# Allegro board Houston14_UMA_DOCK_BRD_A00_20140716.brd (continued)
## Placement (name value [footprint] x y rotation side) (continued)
RV83  2.2K_0402_5%  [R_0402]  153.4 98.36 180 top
RV84  1M_0402_5%  [R_0402]  153.4 99.38 180 top
RV85  1M_0402_5%  [R_0402]  169 102.16 0 top
RV86  10K_0402_5%  [R_0402]  159.04 103.9 270 bottom
RV87  2.2K_0402_5%  [R_0402]  154.01 92.52 0 bottom
RV88  10K_0402_5%  [R_0402]  158.79 86.48 90 top
RV89  3.74K_0402_1%  [R_0402]  159.8 87.39 270 top
RV90  100K_0402_5%  [R_0402]  196.58 100.65 180 bottom
RV91  100K_0402_5%  [R_0402]  182.87 100.4 180 bottom
RV100  4.7K_0402_5%  [R_0402]  146.82 89.17 270 bottom
RV121  4.7K_0402_5%  [R_0402]  178.85 89.27 90 top
RV210  100K_0402_5%  [R_0402]  167.94 84.08 90 top
RV212  100K_0402_5%  [R_0402]  172.19 87.18 180 top
RV250  2.2K_0402_5%  [R_0402]  180.12 89.27 90 top
RV251  2.2K_0402_5%  [R_0402]  181.14 89.27 90 top
RV508  1M_0402_5%  [R_0402]  184.49 99.38 0 bottom
RV509  1M_0402_5%  [R_0402]  170.78 99.38 0 bottom
RV516  2.2K_0402_5%  [R_0402]  154.38 101.54 180 top
RV517  2.2K_0402_5%  [R_0402]  152.49 100.28 0 top
RV518  2.2K_0402_5%  [R_0402]  169.42 97.16 180 top
RV519  2.2K_0402_5%  [R_0402]  160.39 99.21 90 bottom
RZ5  100K_0402_5%  [R_0402]  174.08 82.62 0 top
RZ8  2.2K_0402_5%  [R_0402]  241.03 20.89 180 top
RZ9  2.2K_0402_5%  [R_0402]  241.03 19.88 180 top
RZ10  1M_0402_5%  [R_0402]  241.03 13.27 180 top
RZ14  100K_0402_5%  [R_0402]  276.14 52.85 270 top
RZ15  100K_0402_5%  [R_0402]  272.58 51.17 90 top
RZ16  100K_0402_5%  [R_0402]  180.58 82.87 180 top
RZ17  0_0402_5%  [R0402_0OHM]  183.98 63.31 0 top
RZ18  4.7K_0402_5%  [R_0402]  237.02 34.91 90 top
RZ19  4.7K_0402_5%  [R_0402]  237.02 37.86 270 top
RZ21  33_0402_5%  [R_0402]  242.05 56.96 180 top
RZ22  10K_0402_5%  [R_0402]  243.17 55.95 0 top
RZ24  10K_0402_5%  [R_0402]  253.02 90.95 270 top
RZ25  220_0402_5%  [R_0402]  292.7 42.99 0 bottom
RZ26  33_0402_5%  [R_0402]  183.98 64.33 0 top
RZ27  220_0402_5%  [R_0402]  250.99 90.95 270 top
RZ28  330_0402_5%  [R_0402]  292.77 43.75 0 top
RZ29  33_0402_5%  [R_0402]  183.98 62.3 0 top
RZ30  33_0402_5%  [R_0402]  183.98 60.26 0 top
RZ31  100K_0402_5%  [R_0402]  306.67 87.19 0 bottom
RZ32  150_0402_5%  [R_0402]  310.49 87.86 180 bottom
RZ33  220_0402_5%  [R_0402]  304.53 85.03 180 bottom
RZ34  220_0402_5%  [R_0402]  310.38 84.04 180 bottom
RZ35  33_0402_5%  [R_0402]  183.98 65.34 0 top
RZ37  100K_0402_5%  [R_0402]  279.97 52.86 270 top
RZ38  100K_0402_5%  [R_0402]  273.41 63.9 270 top
RZ39  10K_0402_5%  [R_0402]  284.98 93.03 180 top
RZ40  100K_0402_5%  [R_0402]  270.01 70.07 90 top
RZ41  0_0402_5%  [R_0402]  269.89 65.92 0 top
RZ42  0_0402_5%  [R0402_0OHM]  269.89 66.84 0 top
RZ43  0_0402_5%  [R0402_0OHM]  283.68 80.39 0 bottom
RZ44  0.01_1206_1%  [R_1206]  178.08 77.35 0 top
RZ46  0_0603_5%  [R_0603]  181.8 38.57 90 top
RZ47  0_0603_5%  [R0603_0OHM]  183.06 39.98 270 top
RZ51  0_0402_5%  [R0402_0OHM]  241.48 70.74 0 top
RZ56  0_0402_5%  [R_0402]  282.6 48.95 180 top
RZ57  0_0402_5%  [R0402_0OHM]  282.6 48.05 180 top
SW1  SS3-CMFTQR9_3P  [SW_SS3-CMFTQR9_3P]  228.6 68.89 0 bottom
SW3  SKRBAAE010_4P  [SW_SKRBAAE010_4P]  323.2 94.06 0 top
T8  PAD~D  [TPC12]  170.01 43.47 0 top
T9  PAD~D  [TPC12]  173.27 54.63 0 top
T10  PAD~D  [TPC12]  123.48 62.8 0 top
T11  PAD~D  [TPC12]  123.1 64.2 0 top
T12  PAD~D  [TPC12]  124.24 61.53 0 top
T13  PAD~D  [TPC12]  121.82 64.15 0 top
T14  PAD~D  [TPC12]  125.77 61.53 0 top
T15  PAD~D  [TPC12]  125.01 62.8 0 top
T16  PAD~D  [TPC12]  170.6 56.96 0 top
T21  PAD~D  [TPC12]  173.47 55.4 0 top
T22  PAD~D  [TPC12]  170.61 60.39 0 top
T27  PAD~D  [TPC12]  176.11 53.48 0 top
T28  PAD~D  [TPC12]  124.07 43.2 180 bottom
T29  PAD~D  [TPC12]  121.03 41.34 180 bottom
T30  PAD~D  [TPC12]  125.06 72.13 180 bottom
T31  PAD~D  [TPC12]  126 69.71 180 bottom
T33  PAD~D  [TPC12]  140.94 75.57 180 bottom
T34  PAD~D  [TPC12]  142.6 75.31 180 bottom
T35  PAD~D  [TPC12]  122.25 60.59 0 top
T74  PAD~D  [TPC12]  132.19 61.94 0 top
T75  PAD~D  [TPC12]  132.12 63.54 0 top
T76  PAD~D  [TPC12]  133.79 62.85 0 top
T77  PAD~D  [TPC12]  133.9 64.33 0 top
T87  PAD~D  [TPC12]  256.43 114.21 0 top
T88  PAD~D  [TPC12]  284.01 86.17 0 top
T89  PAD~D  [TPC12]  282.99 87.82 0 top
T96  PAD~D  [TPC12]  261.02 74.23 180 top
T97  PAD~D  [TPC12]  251.83 87.39 180 top
T98  PAD~D  [TPC12]  257.49 86.93 180 top
T99  PAD~D  [TPC12]  251.5 85.92 0 top
T108  PAD~D  [TPC12]  160.41 88.36 0 top
T109  PAD~D  [TPC12]  174.41 64.71 0 top
TL1  MHPC_NS692417  [MHPC_NS692417_24P]  309.39 89.99 180 bottom
UA1  -  [ALC3235-CG_MQFN48_6X6]  29.76 92.61 90 top
UC1  BDW-ULT-DDR3L_BGA1168  [BDW-ULT-DDR3L_BGA_1168P-T]  168.98 70.23 0 bottom
UC2  -  [W25Q64FVSSIQ_SO8]  199.02 55.57 270 bottom
UC3  -  [W25Q32FVSSIQ_SO8]  199.2 66.28 270 bottom
UC4  -  [74AHC1G09GW_TSSOP5]  176.7 58.85 90 top
UC5  TC7SH08FU_SSOP5~D  [TC7SH08FU_SSOP5]  184 52.79 270 top
UC6  TC7SH08FU_SSOP5~D  [TC7SH08FU_SSOP5]  188.95 47.93 90 top
UC7  -  [74CBTLV3126BQ_DHVQFN14_2P5X3]  107.04 35.17 90 top
UC8  -  [74AUP1G07GW_TSSOP5]  169.08 40.56 90 top
UD1  -  [74AUP1G07GW_TSSOP5]  143.17 2.46 90 top
UE1  ECE5048-LZY_DQFN132_11X11~D  [ECE5048-LZY_DQFN132_11X11]  258.17 84.89 180 top
UE2  -  [MEC5085-LZY_DQFN132_11X11]  263.3 55.75 90 top
UI1  SY6288D10CAC_MSOP8  [G547I2P81U_MSOP8]  56.65 104.55 270 top
UI2  SY6288D10CAC_MSOP8  [G547I2P81U_MSOP8]  247.99 117.2 270 bottom
UI3  -  [TPS2544RTER_WQFN16_3X3]  305.32 78.54 270 top
UI4  -  [PI3USB3102ZLEX_TQFN32_6X3]  187.52 92.48 0 top
UI5  -  [NX3DV221GM_XQFN10U10_2X1P55]  162.84 105.2 0 bottom
UL1  WGI218LM-QQ89-B0_QFN48_6X6~D  [WGI217LM-QPN9-A2_QFN48_6X6]  275.7 88.12 270 top
UL2  TC7SH08FU_SSOP5~D  [TC7SH08FU_SSOP5]  285.17 83.82 180 top
UL4  -  [PI3L720ZHEX_TQFN42_9X3P5]  241.55 101.07 0 top
UN1  -  [LNG3DMTR_LGA16_3X3]  286.25 57.74 90 top
UN2  -  [PI3EQX6741STZDEX_TQFN20_4X4]  293.51 58.72 270 top
UN3  TPS22967DSGR_SON8_2X2  [TPS22965DSGR_SON8_2X2]  304.94 53.29 180 top
UR1  -  [OZ777FJ2LN_QFN48_6X6]  306.61 66.02 270 top
UV2  -  [AP2330W-7_SC59-3]  98.03 103.26 180 top
UV4  -  [AP2330W-7_SC59-3]  272.58 108.85 180 top
UV7  -  [PS8338BQFN60GTR-A0_QFN60_5X9]  144.05 91.56 180 bottom
UV8  VMM3320BJGR_BGA168  [VMM3320BJGR_BGA_168P-NH]  156.85 98.38 0 top
UV9  W25X10CVSNIG_SO8  [W25X10BVSNIG_SO8]  151.93 99.93 0 bottom
UV11  -  [PI3C3125LEX_TSSOP14]  187.38 99.72 90 bottom
UV12  -  [PI3C3125LEX_TSSOP14]  173.92 99.72 90 bottom
UV16  TS3V713ELRTGR_WQFN32_6X3  [PI3V713-AZLEX_TQFN32_6X3]  176.09 92.46 0 top
UV24  -  [AP2821KTR-G1_SOT23-5]  85.32 95.27 180 top
UZ1  AT97SC3205_TSSOP28~D  [AT97SC3205_TSSOP28]  193.95 59.09 90 top
UZ2  APE8990GN3B_SON14_2X3  [TPS22966DPUR_SON14_2X3]  267.57 72.96 0 top
UZ3  APE8990GN3B_SON14_2X3  [TPS22966DPUR_SON14_2X3]  275.81 61.54 180 top
UZ5  -  [RT9818A-44GU3_SC70-3]  241.91 54.17 90 top
UZ6  TC7SH08FU_SSOP5~D  [TC7SH08FU_SSOP5]  246.31 53.59 180 top
UZ7  TPS22967DSGR_SON8_2X2  [TPS22965DSGR_SON8_2X2]  177.75 80.57 270 top
UZ8  APE8990GN3B_SON14_2X3  [TPS22966DPUR_SON14_2X3]  184.45 34.86 0 top
UZ9  APE8990GN3B_SON14_2X3  [TPS22966DPUR_SON14_2X3]  215.44 88.32 0 top
UZ10  TC7SH08FU_SSOP5~D  [TC7SH08FU_SSOP5]  295.66 45.15 270 top
UZ11  -  [TC7SH08FU_SSOP5]  285.56 48.18 90 top
YC1  32.768KHZ_12.5PF_9H03220008  [Y_9H03220008_2P]  188 45.26 270 bottom
YC2  24MHZ_12PF_X3G024000DC1H  [Y_X3G024000DC1H_4P]  155.4 82.45 0 bottom
YE1  32.768KHZ_12.5PF_Q13FC135000040  [Y_Q13FC135000040_2P]  261.42 47.82 0 top
YL1  25MHZ_18PF_7V25000034  [Y_7V25000034_4P]  268.86 81.13 90 top
YV2  27MHZ_12PF_X1E000021042600  [Y_X1E000021042600_4P]  148.08 89.3 270 top

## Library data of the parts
C33 PC21 PC22 = C_0805
C42 C43 C319 CA12 CA13 CA54 CC3 CC14 CC15 CC24 CC83 CC97 CC100 CC101 CI38 CI414-CI419 CN3 CN4 CV115 CV118 CV374 CZ65-CZ68 PC20 PC106 PC206 PC311 PC520 PC521 PC732 = C_0402
C263 = C_0402: room: SIM
C294-C316 = C_0402: room: DOCK
C317 C318 = C_0603: room: DOCK
CA1-CA4 = C_0402: room: AJACK
CA5 CA6 = C_0402: room: CAM
CA7 CV1-CV6 CV8 CV10 CV11 CZ1 = C_0402: room: EDP
CA8 CA11 CA17 CA19 CA22-CA24 CA27 CA28 CA30 CA33 CA35 CA41 CA45 CA47 CA50 CV61 CV62 = C_0402: room: CODEC
CA9 CA10 CA16 CA18 CA25 CA26 CA29 CA31 CA43 CA44 CA46 CA48 CA49 CA51-CA53 = C_0603: room: CODEC
CC1 CC2 CC4 CC5 CC8 CC11-CC13 CC17-CC22 CC25-CC28 CC35 CC37 CC40 CC43 CC44 CC48-CC50 CC52-CC54 CC57-CC59 CC61 CC65 CC66 CC68-CC73 CC78 CC80 CC82 = C_0402: room: CPU
CC6 CC7 CC9 CC10 = C_0402: room: SPI
CC23 CC79 CC84 CC85 CC94 CC95 CI420-CI422 CV377-CV380 = C_0603
CC29-CC34 CC36 CC47 CC51 CC55 CC56 CC60 CC62-CC64 = C_0603: room: CPU
CC39 PC207 = C_D2: room: CPU
CC41 CC42 = C_APXK2R5ARA331MF451: room: CPU
CC67 CC77 CC81 = C_1206: room: CPU
CD1-CD11 CD21-CD27 CD30-CD44 CD54-CD60 CD63 CD64 = C_0402: room: MEMORY
CD12-CD19 CD28 CD29 CD45-CD52 CD61 CD62 = C_0603: room: MEMORY
CD20 CD53 = C_D2: room: MEMORY
CE1 CE7 = C_0603: room: SIO
CE2-CE6 CE8 CE9 = C_0402: room: SIO
CE10-CE20 CE22-CE30 CE34 CE40 CE44 CE45 CZ34 CZ35 = C_0402: room: KBC
CE21 CE31 = C_0603: room: KBC
CE32 = C_0603: room: FAN
CE35-CE39 CE46 = C_0402: room: THERMAL
CI1 CI8 CI14 = C_1206: room: USB
CI3-CI5 CI7 CI10 CI12 CI13 CI16 CI17 CI19 CI27 CI28 = C_0402: room: USB
CI6 CI11 = C_0603: room: USB
CL1-CL3 CL5 CL6 CL8-CL11 CL13-CL15 CL25-CL27 CZ62 CZ63 = C_0402: room: LAN
CL4 CL7 CL12 = C_0603: room: LAN
CL16 CL17 CL20 CL21 = C_0603: room: LOM
CL18 = C_0402: room: LOM
CL19 CV13 CV14 CV17 CV18 CV21-CV23 CV26 CV28 CV29 CZ2 = C_0402: room: HDMI
CL22 = C_1808: room: LOM
CMOS1 = SHORTPADS-S: User Part Number: PART#; room: CPU
CN1 = C_0603: room: HDD
CN2 CN13-CN20 CN23-CN26 CN29 CN30 = C_0402: room: HDD
CR1 CR7 CR9 CR14 CR18 CR34 = C_0603: room: OZ777
CR2-CR4 CR6 CR8 CR10 CR13 CR15 CR17 CR19 CR21-CR27 CR31 CR35 = C_0402: room: OZ777
CV7 CV9 CV12 = C_0603: room: EDP
CV27 = C_0603: room: HDMI
CV50-CV59 CV124-CV128 CV144 = C_0402: room: CRT
CV60 CV66 CV69-CV80 CV145-CV150 CV152 CV153 CV156 CV157 = C_0402: room: DP12412
CV82 CV87 CV90 CV94 CV101 = C_0603: room: DP2320
CV83-CV86 CV88 CV89 CV91-CV93 CV95-CV100 CV102-CV111 CV113 CV114 = C_0402: room: DP2320
CV119-CV123 = C_0402: room: DP125
CZ4-CZ7 CZ9 = C_0402: room: TPM
CZ10-CZ12 = C_0402: room: USH
CZ13-CZ18 CZ20-CZ22 CZ32 CZ33 CZ58 CZ59 = C_0402: room: WLAN
CZ19 = C_0603: room: WLAN
CZ23-CZ25 CZ41 CZ49 CZ50 = C_0402: room: 3.3V_SUS_SOURCE
CZ27-CZ31 = C_0402: room: KB_TP
CZ36 CZ37 CZ40 CZ44 CZ47 = C_0402: room: 3.3V_ALW_PCH_SOURCE
CZ38 = C_0603: room: 3.3V_SUS_SOURCE
CZ39 = C_0402: room: 1.05V_RUN_SOURCE
CZ42 CZ43 = C_0402: room: 3.3V_M_SOURCE
CZ45 = C_0402: room: 5V_RUN_SOURCE
CZ46 = C_0402: room: 3.3V_RUN_SOURCE
CZ48 = C_0402: room: LED
CZ51-CZ53 CZ55 = C_0402: room: WWAN
CZ54 = C_0603: room: WWAN
CZ56 = C_MP6VLPB150MB4: room: WWAN
CZ57 = C_B2: room: WWAN
CZ64 = C_0402: room: +1.05V_RUN_SOURCE
D19 = RB751S40T1G_SOD523-2: room: DOCK
D20 = L30ESD24VC3-2_SOT23-3: room: DOCK
DA1-DA3 = L03ESDL5V0CC3-2_SOT23-3: room: AJACK
DA4 DA5 = RB751S40T1G_SOD523-2: room: CODEC
DA6 DA7 = L03ESDL5V0CC3-2_SOT23-3: room: CODEC
DE1 = RB751S40T1G_SOD523-2: room: FAN
DI1 DI4 DI6 = L05ESDL5V0NA-4_SLP2510P8-10-9: room: USB
DI2 DI3 DI5 = AZC199-02SPR7G_SOT23-3: room: USB
DV1-DV3 = BAT54CW_SOT323-3: room: EDP
DV4 = AZC199-02SPR7G_SOT23-3: room: EDP
DV5 DV6 = PJDLC05C_SOT23-3: room: CRT
DZ1 DZ2 DZ5 DZ6 = RB751S40T1G_SOD523-2: room: WLAN
DZ3 DZ4 = RB751S40T1G_SOD523-2: room: LED
FD1-FD4 = FIDUCIAL_C40M80: room: LED
H1 H3 H6-H8 = H_2P8: room: LED
H2 H18 = H_2P4: room: LED
H4 H19 = H_4P0: room: LED
H9 H22 = H_2P8
H10 = H_3P8
H11-H13 = H_3P8: room: LED
H15 H17 = H_3P2: room: LED
H20 = H_2P5N: room: LED
H24 = H_3P3
JAPS1 = ACES_50506-01841-P01_18P: room: CPU
JCRT1 = C-H_13-122015XXCP-A_15P-T: room: CRT
JDEG1 JLPDE1 = HB_A531015-SCHR21_10P: room: SIO
JDIMM1 JDIMM2 = BELLW_80001-1021_204P: room: CPU
JDOCK1 = JAE_WD2F144WB5R400_144P: room: DOCK
JEDP1 = ACES_50398-04041-001_40P: room: EDP
JFAN1 = ACES_50271-0040N-001_4P: room: THERMAL
JHDMI1 = CONCR_099BKAC19YBLCNF_19P-T: room: HDMI
JHP1 = SINGA_2SJ3080-039111F_6P-T: room: CODEC
JKBTP1 = E-T_6705K-Y16N-00L_16P: room: SIO
JLED1 = E-T_6705K-Y10N-00L_10P-T: room: LED
JLOM1 = SANTA_130456-511_13P-T: room: LAN
JNGFF1 = BELLW_80148-3221_67P-T: room: WLAN
JNGFF2 = BELLW_80149-4221_67P-T: room: WWAN
JRTC1 = TYCO_2-1775293-2_2P: room: ETY-ROOM
JSATA1 = STARC_115B20-000000-G2-R_20P-T: room: HDD
JSD1 = T-SOL_156-2000302608_19P_NR-S: room: OZ777
JSIM1 = T-SOL_159-1201300600_8P-T: room: WWAN
JSPI1 = E-T_6705K-Y20N-00L_20P: room: FLASH ROM
JSPK1 = ACES_50279-0040N-001_4P: room: CODEC
JTAG1 = SHORTPADS: User Part Number: PART#; room: KBC
JUSB1 JUSB2 = C-K_26210-8K1A-02_9P-T: room: USB
JUSB3 = SINGA_2UB1641-000111F_9P-T: room: USB
JUSH1 = E-T_6705K-Y20N-00L_20P: room: TPM
JXDP1 = SAMTE_BSH-030-01-L-D-A_60P: room: CPU
LA2 LA3 = MURAT_BLM15BD601SN1D_2P: room: AJACK
LA5 = MURAT_BLM15PX600SN1D_2P: room: CODEC
LA6-LA9 = MURAT_BLM15PX330SN1D_2P: room: CODEC
LA10 LA11 = MURAT_BLM15PX330SN1D_2P
LC1-LC5 = MURAT_LQM2MPN2R2NG0L_2P: room: CPU
LED3 = LED_LTW-193ZDS5_2P: room: LED
LI1-LI9 = MURAT_DLW21HN900HQ2L_4P: room: USB
LL1 = TAIYO_BRC2012T4R7MD_2P: room: LAN
LV1 = MURAT_BLM15BB221SN1D_2P: room: EDP
LV3 LV6 LV9 LV12 = MURAT_DLW21HN900HQ2L_4P: room: HDMI
LV16-LV18 = MURAT_BLM15BB470SN1D_2P: room: CRT
LV19 LV20 = MURAT_BLM15AG121SN1D_L0402_2P: room: CRT
LV22-LV25 = MURAT_BLM15PX181SN1D_2P: room: DP2320
LV27 = MURAT_DLW21HN900HQ2L_4P: room: TOUCH
LZ1 = MURAT_DLW21HN900HQ2L_4P: room: CAM
MIC1 = KNOW_SPM1437HM4H-6_6P: room: CPU
PBATT1 = DEREN_40-42251-01001RHF_10P-T: room: ETY-ROOM
PC1 PC9 = C_0603: room: P_DCIN
PC3 PC4 = C_0402: room: P_DCIN
PC5 = C_0805: room: P_DCIN
PC10 PC101 PC102 PC200 PC201 PC205 PC303 PC305-PC308 PC401 PC404 = C_0805: room: ETY-ROOM
PC100 PC109-PC111 PC114 PC117-PC119 PC204 PC209 PC211 PC301 PC302 PC309 PC310 PC500 PC505 PC507 PC509 PC510 = C_0603: room: ETY-ROOM
PC105 PC203 PC212 PC214 PC215 PC300 PC304 PC400 PC402 PC403 PC502-PC504 PC506 PC511-PC514 PC737 PC741 = C_0402: room: ETY-ROOM
PC113 PC115 = C_APXK6R3ARA221MF451: room: 3V5V
PC208 PC721 = C_0603: room: ADP3209
PC213 PC501 PC805 PC810 = C_0402: room: CPU_CORE
PC508 = C_0603: room: CPU_CORE
PC515-PC518 = C_0805: room: CPU_CORE
PC519 = C_D: room: ETY-ROOM
PC700 PC701 PC710 PC712 PC722 = C_0603: room: CHARGER
PC702 PC703 PC711 PC713 PC718 PC719 PC726-PC728 = C_0402: room: CHARGER
PC704-PC709 PC714-PC717 PC723-PC725 = C_0805: room: CHARGER
PC729 PC813 PC815 PC816 = C_0603: room: P_SELECTOR
PC807 = C_0805: room: P_SELECTOR
PC809 PC817 = C_0402: room: P_SELECTOR
PC900-PC904 PC913-PC917 = C_0805: room: CPU
PC966 = C_D2
PD1 PD2 = TVNST52302AB0_SOT523-3: room: ETY-ROOM
PD3 = BAS40-05W_SC70-3: room: ETY-ROOM
PD4 = RB751V-40_SOD323-2: room: P_DCIN
PD5 = AZC199-02SPR7G_SOT23-3
PD702 PD704 PD705 = SDMK0340L-7-F_SOD323-2
PD800 PD808 = PDS5100H-13_POWERDI5-3: room: P_SELECTOR
PD813 = SDMK0340L-7-F_SOD323-2: room: ETY-ROOM
PD815 = BAT54CW_SOT323-3: room: ETY-ROOM
PD817 = BAT54CW_SOT323-3
PH500 PH501 PR100-PR102 PR104-PR107 PR114 PR201 PR205 PR206 PR209 PR303 PR307 PR310 PR400-PR403 PR500 PR502 PR512-PR516 PR527-PR529 PR706 PR707 PR722 PR737 PR738 PR745 PR864 = R_0402: room: ETY-ROOM
PJP1 PJP100-PJP102 PJP203 PJP204 PJP300 = JUMP_43X118: room: ETY-ROOM
PJP4 PJP5 = JUMP_43X39: room: HDD
PJP6 PJP9 PJP13 PJP26 = JUMP_43X79: room: CODEC
PJP7 PJP29 PJP35 = JUMP_43X39
PJP10 PJP17 PJP20 PJP24 PJP25 PJP32 = JUMP_43X39: room: CODEC
PJP11 = JUMP_43X39: room: TPM
PJP12 = JUMP_43X39: room: LAN
PJP14 = JUMP_43X39: room: SIO
PJP15 PJP16 = JUMP_43X39: room: KBC
PJP18 PJP21 PJP22 = JUMP_43X118: room: CODEC
PJP23 = JUMP_43X39: room: CPU
PJP36 = JUMP_43X118
PJP200 PJP302 = JUMP_43X79: room: DDR_VTT_0.75V
PJP201 PJP202 PJP400 PJP401 = JUMP_43X39: room: VGA_CORE
PJP500 = JUMP_43X118: room: CHARGER
PJP700 = JUMP_43X118-NPM: room: CHARGER
PJP701 = JUMP_43X39: room: CHARGER
PJPDC1 = CVILU_CI0805M1HRC-NH_5P-T: room: ETY-ROOM
PL1 PL2 PL4 = TAIYO_FBMJ4516HS720NT_2P: room: P_DCIN
PL3 = MURAT_BLM15AG102SN1D_2P: room: P_DCIN
PL100 = L_5X5X3_M_2P-NPM: room: ETY-ROOM
PL101 PL200 = PANAS_ETQP3W2R2WFN_2P: room: ETY-ROOM
PL102 = PANAS_ETQP3W2R2WFN_2P: room: VDDCI
PL301 PL700 = L_5X5X3_M_2P: room: ETY-ROOM
PL500 = PANAS_ETQP4LR15AFM_4P: room: ETY-ROOM
PL501 = FBMA-L11-453215800LMA90T_2P-NPM: room: CPU_CORE
PL701 = TOKO_FDVE1040-H-3R3M-P3_2P: room: ETY-ROOM
PQ1 = SI2301CDS-T1-GE3_SOT23-3: room: P_DCIN
PQ2 = FDV301N-G_SOT23-3: room: P_DCIN
PQ3 = MMST3904-7-F_SOT323-3: room: P_DCIN
PQ4 PQ826 = FDMC6679AZ_MLP8-5: room: ETY-ROOM
PQ6 = IMD2AT-108_SC74-6: room: ETY-ROOM
PQ100 PQ101 = SIS412DN-T1-GE3_POWERPAK8-5: room: ETY-ROOM
PQ102 PQ103 = SI7716ADN-T1-GE3_POWERPAK8-5: room: ETY-ROOM
PQ200 = SIS412DN-T1-GE3_POWERPAK8-5
PQ201 = SI7716ADN-T1-GE3_POWERPAK8-5
PQ700 = SI4835DDY-T1-GE3_SO8: room: CHARGER
PQ701 PQ702 = NTR4502PT1G_SOT23-3: room: ETY-ROOM
PQ703 = NTGD4161PT1G_TSOP6: room: ETY-ROOM
PQ705 = AON6970_DFN5X6D-8-7
PQ800 = SI4835DDY-T1-GE3_SO8: room: ETY-ROOM
PQ806 PQ813 = DMN65D8LDW-7_SOT363-6: room: P_SELECTOR
PQ810 PQ815 = FDS6679AZ-G_SO8: room: ETY-ROOM
PQ814 = NTR4502PT1G_SOT23-3: room: P_SELECTOR
PQ816 = DMN65D8LW-7_SOT323-3: room: DC_IN
PQ817 = DMN65D8LDW-7_SOT363-6: room: ETY-ROOM
PQ829 = SI2301CDS-T1-GE3_SOT23-3: room: P_SELECTOR
PQ832 = DMN65D8LW-7_SOT323-3: room: ETY-ROOM
PR1 PR2 PR7-PR15 PR17 PR18 PR863 = R_0402: room: P_DCIN
PR6 PR811 PR812 PR842 PR843 PR845 PR848 PR850 PR851 PR853-PR855 PR857 PR859 = R0402_0OHM: room: P_DCIN
PR16 = R_0805: room: P_DCIN
PR103 PR108 PR113 PR207 PR210 PR520 PR531 PR532 PR534 PR536 PR539 PR700 PR702 PR895 = R0402_0OHM: room: ETY-ROOM
PR109 PR110 PR200 PR517 PR519 = R_0603: room: CPU_CORE
PR111 PR112 PR203 PR305 = R_1206: room: ETY-ROOM
PR202 PR526 = R_0603: room: ETY-ROOM
PR204 RZ47 = R0603_0OHM
PR306 PR308 = R_0402: room: 1P5V
PR309 PR315 PR518 PR524 PR525 PR788 PR799 R6 R41 R273 RA40 RA44 RC27 RC92 RC247 RC300-RC306 RE84 RE86 RE88 RE274 RE276 RE277 RE280 RE281 RE283 RL29 RL30 RN6 RN7 RN19-RN25 RR15 RV100 RV210 RV212 RV250 RV251 RV516-RV519 RZ41 RZ56 = R_0402
PR312 = R0603_0OHM: room: CPU_CORE
PR313 RA45 RC26 RE275 RE279 RE282 RZ42 RZ43 RZ51 RZ57 = R0402_0OHM
PR501 PR503-PR511 PR521 PR523 PR535 = R_0402: room: GPU_CORE
PR522 = R_1206: room: CPU_CORE
PR701 PR721 = R_1206_4P-D: room: ETY-ROOM
PR703 PR710 PR711 PR713 PR715 PR725 PR729 PR740 = R_0402: room: CHARGER
PR704 PR705 PR709 PR714 PR716-PR718 PR720 PR728 PR743 = R0402_0OHM: room: CHARGER
PR708 PR726 = R_1206: room: CHARGER
PR712 = R_0603: room: 3V5V
PR723 = R_0603: room: CHARGER
PR810 PR813-PR816 PR818 PR819 PR822 PR826-PR830 PR844 PR846 PR858 PR874 = R_0402: room: P_SELECTOR
PR831 PR832 PR838 PR847 PR860 = R_0603: room: P_DCIN
PR835 = R_0805: room: P_SELECTOR
PRP2 = RP_0804_8P4R: room: ETY-ROOM
PT1 PT2 T99 T109 = TPC12
PU1 = TS5A63157DCKR_SC70-6: room: P_DCIN
PU100 = TPS51285BRUKR_QFN20_3X3: room: ETY-ROOM
PU200 = RT8207MZQW_WQFN20_3X3: room: ETY-ROOM
PU300 = SY8208DQNC_QFN10_3X3: room: ETY-ROOM
PU400 = APL5930KAI-TRG_SO8: room: ETY-ROOM
PU500 = TPS51622RSM_QFN32_4X4: room: CPU_CORE
PU501 = CSD97374CQ4M_SON8_3P5X4P5: room: ETY-ROOM
PU700 = BQ24715URUYR_WQFN28_4X4: room: ETY-ROOM
PU800 = CD3301RHHR_QFN36_6X6: room: P_SELECTOR
PU804 PU806 = TC7SH08FU_SSOP5: room: PCH
QA1 = L2N7002WT1G_SC-70-3: room: CODEC
QA2 QA3 = DMN66D0LDW-7_SOT363-6: room: CODEC
QC1 = DMN66D0LDW-7_SOT363-6: room: CPU
QD1 = L2N7002WT1G_SC-70-3: room: MEMORY
QE2 = DMN66D0LDW-7_SOT363-6: room: THERMAL
QE3-QE7 = MMBT3904WT1G_SC70-3: room: THERMAL
QL1 QL2 = DMN66D0LDW-7_SOT363-6: room: LAN
QN1 = DMN66D0LDW-7_SOT363-6: room: HDD
QV1 = AO6405_TSOP6: room: EDP
QV2 = L2N7002WT1G_SC-70-3: room: EDP
QV3 = DMN66D0LDW-7_SOT363-6: room: HDMI
QV4 QV5 = L2N7002WT1G_SC-70-3: room: HDMI
QV7 = L2N7002WT1G_SC-70-3: room: TOUCH
QV8 = LP2301ALT1G_SOT23-3: room: TOUCH
QV9 QV10 = L2N7002WT1G_SC-70-3: room: DP125
QV11 = L2N7002WT1G_SC-70-3
QV20 = SI3456DDV-T1-GE3_TSOP6
QV21 = DMN66D0LDW-7_SOT363-6
QZ1 = LP2301ALT1G_SOT23-3: room: CAM
QZ2 QZ11 = DMN66D0LDW-7_SOT363-6: room: WLAN
QZ3 QZ7 = DMN66D0LDW-7_SOT363-6: room: LED
QZ4 QZ9 = DDTA114EUA-7-F_SOT323-3: room: LED
QZ6 = SI3456DDV-T1-GE3_TSOP6: room: 1.05V_MODPHY
QZ10 = DMN66D0LDW-7_SOT363-6: room: 1.05V_MODPHY
R252-R268 R271 R272 = R_0402: room: DOCK
RA1 RA2 = R_0402: room: AJACK
RA3 RA4 = R0603_0OHM: room: CODEC
RA5-RA9 RA12-RA14 RA17 RA18 RA21 RA26-RA32 RA38 = R_0402: room: CODEC
RA24 RA25 RV50-RV58 RV60-RV65 RV67-RV72 = R_0402: room: DP12412
RA35-RA37 = R0402_0OHM: room: CODEC
RA39 = R0805_0OHM: room: CODEC
RC1 RC2 RC7-RC11 RC14-RC23 RC25 RC33 RC34 RC63 RC66-RC70 RC72 RC74 RC78-RC82 RC91 RC95 RC98 RC99 RC102 RC103 RC106 RC109 RC112-RC133 RC136 RC139-RC142 RC149 RC152 RC153 RC155 RC156 RC158 RC160 RC163 RC164 RC171 RC174-RC176 RC178-RC181 RC183-RC195 RC197-RC199 RC201 RC202 RC204 RC207-RC209 RC211 RC213 RC216 RC218 RC240-RC243 RC245 = R_0402: room: CPU
RC4 RC65 RC77 RC87-RC89 RC161 RC212 RC217 RC219 = R0402_0OHM: room: CPU
RC29 RC31 RC224-RC231 = R_0402: room: FLASH ROM
RC35 RC50 = R0402_0OHM: room: SPI
RC38 RC55 RC61 RC62 = R_0402: room: SPI
RC196 = R_0603: room: CPU
RD2 RD4-RD7 RD9-RD14 RD18-RD25 = R_0402: room: MEMORY
RD15 RD16 RD27 RD28 = R0402_0OHM: room: MEMORY
RE5 RE8-RE12 RE17 RE20 RE21 RE24-RE27 = R_0402: room: SIO
RE31 RE33 RE35-RE37 RE42 RE43 RE48 RE51 RE55-RE58 RE60 RE62-RE68 RE71-RE75 RE78 RE79 RE81 RE82 RZ21 = R_0402: room: KBC
RE32 RE59 RE61 = R0402_0OHM: room: KBC
RE69 RE70 RE77 = R_0402: room: THERMAL
RE83 RE85 RZ38 RZ40 = R_0402: room: 3.3V_ALW_PCH_1.05V_RUN_SOURCE
RI13 RI14 = R_0402: room: USB
RL1 RL2 RL4-RL6 RL9 RL12 RL13 = R_0402: room: LAN
RL3 RL7 RL10 = R0402_0OHM: room: LAN
RL8 = R0603_0OHM: room: LAN
RL11 RV73-RV89 RZ22 = R_0402: room: DP2320
RL14-RL20 = R_0402: room: LOM
RL21-RL28 RZ46 = R_0603
RN1-RN5 RN8-RN14 RN16 RN18 = R_0402: room: HDD
RPC1-RPC12 RPC14-RPC20 = RP_0804_8P4R: room: CPU
RPE2-RPE10 = RP_0804_8P4R: room: KBC
RPV1 RPV2 = RP_0804_8P4R: room: DP2320
RR1 RR2 RR5 RR6 RR8 RR11 = R_0402: room: OZ777
RR3 RR4 = R0402_0OHM: room: OZ777
RV1-RV6 = R_0402: room: EDP
RV7-RV20 = R_0402: room: HDMI
RV32-RV38 RV121 = R_0402: room: CRT
RV90 RV91 RV508 RV509 = R_0402: room: DP125
RZ5 RZ16 = R_0402: room: 1.05V_MODPHY
RZ8-RZ10 = R_0402: room: USH
RZ14 RZ15 RZ37 = R_0402: room: WLAN
RZ17 = R0402_0OHM: room: TPM
RZ18 RZ19 = R_0402: room: KB_TP
RZ24 RZ25 RZ27 RZ28 RZ31-RZ34 = R_0402: room: LED
RZ26 RZ29 RZ30 RZ35 = R_0402: room: TPM
RZ39 = R_0402: room: WWAN
RZ44 = R_1206
SW1 = SW_SS3-CMFTQR9_3P: room: CPU
SW3 = SW_SKRBAAE010_4P: room: LED
T8-T16 T21 T22 T27-T31 T33-T35 T74-T77 T108 = TPC12: room: CPU
T87 = TPC12: room: CRT
T88 T89 = TPC12: room: LAN
T96-T98 = TPC12: room: SIO
TL1 = MHPC_NS692417_24P: room: LOM
UA1 = ALC3235-CG_MQFN48_6X6: room: CODEC
UC1 = BDW-ULT-DDR3L_BGA_1168P-T: room: CPU
UC2 = W25Q64FVSSIQ_SO8: room: SPI
UC3 = W25Q32FVSSIQ_SO8: room: SPI
UC4 = 74AHC1G09GW_TSSOP5: room: CPU
UC5 UC6 = TC7SH08FU_SSOP5: room: CPU
UC7 = 74CBTLV3126BQ_DHVQFN14_2P5X3: room: CPU
UC8 UD1 = 74AUP1G07GW_TSSOP5: room: CPU
UE1 = ECE5048-LZY_DQFN132_11X11: room: SIO
UE2 = MEC5085-LZY_DQFN132_11X11: room: KBC
UI1 UI2 = G547I2P81U_MSOP8: room: USB
UI3 = TPS2544RTER_WQFN16_3X3: room: USB
UI4 = PI3USB3102ZLEX_TQFN32_6X3: room: USB
UI5 = NX3DV221GM_XQFN10U10_2X1P55: room: USB
UL1 = WGI217LM-QPN9-A2_QFN48_6X6: room: LAN
UL2 = TC7SH08FU_SSOP5: room: LAN
UL4 = PI3L720ZHEX_TQFN42_9X3P5: room: LAN
UN1 = LNG3DMTR_LGA16_3X3: room: HDD
UN2 = PI3EQX6741STZDEX_TQFN20_4X4: room: OZ777
UN3 = TPS22965DSGR_SON8_2X2
UR1 = OZ777FJ2LN_QFN48_6X6: room: HDD
UV2 = AP2330W-7_SC59-3: room: HDMI
UV4 = AP2330W-7_SC59-3: room: CRT
UV7 = PS8338BQFN60GTR-A0_QFN60_5X9: room: DP125
UV8 = VMM3320BJGR_BGA_168P-NH: room: DP125
UV9 = W25X10BVSNIG_SO8: room: DP125
UV11 UV12 = PI3C3125LEX_TSSOP14: room: DP125
UV16 = PI3V713-AZLEX_TQFN32_6X3: room: CRT
UV24 = AP2821KTR-G1_SOT23-5
UZ1 = AT97SC3205_TSSOP28: room: TPM
UZ2 UZ8 = TPS22966DPUR_SON14_2X3: room: 3.3V_SUS_M_SOURCE
UZ3 = TPS22966DPUR_SON14_2X3: room: LAN
UZ5 = RT9818A-44GU3_SC70-3: room: KBC
UZ6 = TC7SH08FU_SSOP5: room: KBC
UZ7 = TPS22965DSGR_SON8_2X2: room: 3.3V_SUS_M_SOURCE
UZ9 = TPS22966DPUR_SON14_2X3: room: 3.3V_5V_RUN_SOURCE
UZ10 = TC7SH08FU_SSOP5: room: LED
UZ11 = TC7SH08FU_SSOP5
YC1 = Y_9H03220008_2P: room: CPU
YC2 = Y_X3G024000DC1H_4P: room: CPU
YE1 = Y_Q13FC135000040_2P: room: KBC
YL1 = Y_7V25000034_4P: room: LAN
YV2 = Y_X1E000021042600_4P: room: DP2320

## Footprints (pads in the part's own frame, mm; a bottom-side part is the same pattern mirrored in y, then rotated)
74AHC1G09GW_TSSOP5
  oval 0.381x1.346 smd: 1(0,0) 2(0.65,0) 3(1.3,0) 4(1.3,1.79) 5(0,1.79)
74AUP1G07GW_TSSOP5
  oval 0.381x1.346 smd: 1(0,0) 2(0.65,0) 3(1.3,0) 4(1.3,1.79) 5(0,1.79)
74CBTLV3126BQ_DHVQFN14_2P5X3
  oval 1.041x0.254 smd: 1(0,0) 7(2.95,0) 8(2.95,0.5) 14(0,0.5)
  oval 0.254x1.041 smd: 2(0.475,-0.975) 3(0.975,-0.975) 4(1.475,-0.975) 5(1.975,-0.975) 6(2.475,-0.975) 9(2.475,1.475) 10(1.975,1.475) 11(1.475,1.475) 12(0.975,1.475) 13(0.475,1.475)
  rect 1.499x0.991 smd: 15(1.475,0.25)
ACES_50271-0040N-001_4P
  oval 0.787x1.6 smd: 1(0,0) 2(-1.25,0) 3(-2.5,0) 4(-3.75,0)
  rect 2.108x2.997 smd: 5(2.55,-2.9) 6(-6.3,-2.9)
ACES_50279-0040N-001_4P
  oval 0.787x1.905 smd: 1(0,0) 2(1.25,0) 3(2.5,0) 4(3.75,0)
  rect 1.295x3.353 smd: 5(6.6,-4.925) 6(-2.85,-4.925)
ACES_50398-04041-001_40P
  oval 0.254x1.295 smd: 1(0,0) 2(0.5,0) 3(1,0) 4(1.5,0) 5(2,0) 6(2.5,0) 7(3,0) 8(3.5,0) 9(4,0) 10(4.5,0) 11(5,0) 12(5.5,0) 13(6,0) 14(6.5,0) 15(7,0) 16(7.5,0) 17(8,0) 18(8.5,0) 19(9,0) 20(9.5,0) 21(10,0) 22(10.5,0) 23(11,0) 24(11.5,0) 25(12,0) 26(12.5,0) 27(13,0) 28(13.5,0) 29(14,0) 30(14.5,0) 31(15,0) 32(15.5,0) 33(16,0) 34(16.5,0) 35(17,0) 36(17.5,0) 37(18,0) 38(18.5,0) 39(19,0) 40(19.5,0)
  rect 1.194x3.2 smd: 41(-2.4,1.95) 45(21.9,1.95)
  rect 2.311x1.295 smd: 42(0.85,3.9) 43(9.75,3.9) 44(18.65,3.9)
ACES_50506-01841-P01_18P
  oval 0.305x0.889 smd: 1(0,0) 2(0.5,0) 3(1,0) 4(1.5,0) 5(2,0) 6(2.5,0) 7(3,0) 8(3.5,0) 9(4,0) 10(4.5,0) 11(5,0) 12(5.5,0) 13(6,0) 14(6.5,0) 15(7,0) 16(7.5,0) 17(8,0) 18(8.5,0)
  rect 0.991x2.007 smd: 19(-2.1,-3.05) 20(10.6,-3.05)
ALC3235-CG_MQFN48_6X6
  oval 0.203x0.889 smd: 1(0,0) 2(0.4,0) 3(0.8,0) 4(1.2,0) 5(1.6,0) 6(2,0) 7(2.4,0) 8(2.8,0) 9(3.2,0) 10(3.6,0) 11(4,0) 12(4.4,0) 25(4.4,6.1) 26(4,6.1) 27(3.6,6.1) 28(3.2,6.1) 29(2.8,6.1) 30(2.4,6.1) 31(2,6.1) 32(1.6,6.1) 33(1.2,6.1) 34(0.8,6.1) 35(0.4,6.1) 36(0,6.1)
  oval 0.889x0.203 smd: 13(5.25,0.85) 14(5.25,1.25) 15(5.25,1.65) 16(5.25,2.05) 17(5.25,2.45) 18(5.25,2.85) 19(5.25,3.25) 20(5.25,3.65) 21(5.25,4.05) 22(5.25,4.45) 23(5.25,4.85) 24(5.25,5.25) 37(-0.85,5.25) 38(-0.85,4.85) 39(-0.85,4.45) 40(-0.85,4.05) 41(-0.85,3.65) 42(-0.85,3.25) 43(-0.85,2.85) 44(-0.85,2.45) 45(-0.85,2.05) 46(-0.85,1.65) 47(-0.85,1.25) 48(-0.85,0.85)
  rect 4.394x4.394 smd: 49(2.2,3.05)
AO6405_TSOP6
  oval 0.508x1.473 smd: 1(0,0) 2(0.95,0) 3(1.9,0) 4(1.9,2.35) 5(0.95,2.35) 6(0,2.35)
AON6970_DFN5X6D-8-7
  oval 0.66x0.635 smd: 1(0,0) 3(3.81,5.67) 4(2.54,5.67) 5(1.27,5.67) 6(0,5.67)
  custom 0.485x0.485 smd: 2(1.905,0.655)
  rect 3.988x2.667 smd: 7(1.905,3.62)
AP2330W-7_SC59-3
  oval 0.787x0.991 smd: 1(0,0) 2(-0.95,-2.4) 3(0.95,-2.4)
AP2821KTR-G1_SOT23-5
  oval 0.508x0.787 smd: 1(0,0) 2(0.95,0) 3(1.9,0) 4(1.9,2.4) 5(0,2.4)
APL5930KAI-TRG_SO8
  oval 0.635x1.854 smd: 1(0,0) 2(1.27,0) 3(2.54,0) 4(3.81,0) 5(3.81,5.165) 6(2.54,5.165) 7(1.27,5.165) 8(0,5.165)
  rect 2.87x2.489 smd: 9(1.905,2.582)
AT97SC3205_TSSOP28
  oval 0.381x1.626 smd: 1(0,0) 2(0.65,0) 3(1.3,0) 4(1.95,0) 5(2.6,0) 6(3.25,0) 7(3.9,0) 8(4.55,0) 9(5.2,0) 10(5.85,0) 11(6.5,0) 12(7.15,0) 13(7.8,0) 14(8.45,0) 15(8.45,5.8) 16(7.8,5.8) 17(7.15,5.8) 18(6.5,5.8) 19(5.85,5.8) 20(5.2,5.8) 21(4.55,5.8) 22(3.9,5.8) 23(3.25,5.8) 24(2.6,5.8) 25(1.95,5.8) 26(1.3,5.8) 27(0.65,5.8) 28(0,5.8)
AZC199-02SPR7G_SOT23-3
  oval 1.016x1.524 smd: 1(0,0) 2(0.965,2.083) 3(-0.965,2.083)
BAS40-05W_SC70-3
  oval 0.508x0.559 smd: 1(0,0) 2(-0.65,-1.85) 3(0.65,-1.85)
BAT54CW_SOT323-3
  oval 0.61x0.559 smd: 1(0,0) 2(-0.65,-1.85) 3(0.65,-1.85)
BDW-ULT-DDR3L_BGA_1168P-T
  round 0.508 smd: A3(-1.137,0) A62(-38.036,0) AW1(0,22.042) AW63(-38.628,22.057) AY2(-0.543,22.628) AY62(-38.062,22.628) B2(-0.508,0.508) B63(-38.628,0.592) C1(0,1.137)
  round 0.381 smd: A4(-1.894,0) A5(-2.554,0) A6(-3.75,0) A59(-35.9,0) A60(-36.726,0) A61(-37.386,0) AA9(-5.032,11.576) AA21(-11.688,11.489) AA23(-13.115,11.489) AA58(-35.377,11.33) AB10(-5.476,12.053) AB20(-11.18,11.896) AB21(-11.688,12.302) AB22(-12.607,11.896) AB23(-13.115,12.302) AB57(-35.057,11.98) AC9(-5.032,12.529) AC20(-11.18,12.709) AC22(-12.607,12.709) AC58(-35.377,12.63) AD10(-5.476,13.005) AD21(-11.688,13.115) AD23(-13.115,13.115) AD57(-35.057,13.28) AE9(-5.032,13.481) AE10(-5.476,13.958) AE20(-11.18,13.521) AE21(-11.688,13.928) AE22(-12.607,13.521) AE23(-13.115,13.928) AE58(-35.377,13.931) AF9(-5.032,14.434) AF11(-6.059,14.282) AF12(-6.872,14.282) AF14(-7.685,14.282) AF15(-8.497,14.282) AF17(-9.31,14.282) AF18(-10.123,14.282) AF20(-10.936,14.282) AF22(-12.607,14.334) AG10(-5.653,14.79) AG11(-6.465,14.79) AG13(-7.278,14.79) AG14(-8.091,14.79) AG16(-8.904,14.79) AG17(-9.717,14.79) AG19(-10.529,14.79) AG20(-11.342,14.79) AG23(-13.115,14.741) AG57(-35.057,14.581) AG58(-35.692,15.009) AH22(-12.607,15.147) AH24(-13.92,15.289) AH26(-15.22,15.289) AH28(-16.521,15.289) AH30(-17.821,15.289) AH32(-19.122,15.289) AH34(-20.422,15.289) AH36(-21.723,15.289) AH38(-23.023,15.289) AH40(-24.324,15.289) AH42(-25.624,15.289) AH44(-26.925,15.289) AH46(-28.225,15.289) AH49(-29.526,15.289) AH51(-30.826,15.289) AH53(-32.127,15.289) AH55(-33.427,15.289) AH57(-34.728,15.289) AJ23(-13.115,15.553) AJ25(-14.57,15.614) AJ27(-15.871,15.614) AJ29(-17.171,15.614) AJ31(-18.472,15.614) AJ33(-19.772,15.614) AJ35(-21.073,15.614) AJ37(-22.373,15.614) AJ39(-23.674,15.614) AJ41(-24.974,15.614) AJ43(-26.275,15.614) AJ45(-27.575,15.614) AJ47(-28.875,15.614) AJ50(-30.176,15.614) AJ52(-31.476,15.614) AJ54(-32.777,15.614) AJ56(-34.077,15.614) AJ58(-35.378,15.614) AT1(0,19.997) AT63(-38.628,19.848) AU1(0,20.657) AU63(-38.628,20.673) AV1(0,21.318) AV2(-0.66,21.308) AV62(-37.978,21.318) AV63(-38.628,21.333) AW2(-0.66,21.968) AW3(-1.321,21.968) AW61(-37.328,21.978) AW62(-37.978,21.978) AY3(-1.267,22.628) AY4(-1.928,22.628) AY5(-2.588,22.628) AY59(-36.088,22.628) AY60(-36.748,22.628) AY61(-37.409,22.628) B3(-1.259,0.65) B61(-37.315,0.66) B62(-37.978,0.724) C2(-0.65,1.259) C62(-37.978,1.384) C63(-38.628,1.316) D1(0,1.861) D63(-38.628,1.976) E1(0,2.522) E23(-13.333,2.601) E25(-14.714,2.601) E27(-15.84,2.601) E29(-17.221,2.601) E31(-18.348,2.601) E33(-19.729,2.601) E35(-20.855,2.601) E37(-22.236,2.601) E39(-23.363,2.601) E41(-24.744,2.601) E43(-25.87,2.601) E45(-27.251,2.601) E47(-28.378,2.601) E49(-29.759,2.601) E51(-30.885,2.601) E53(-32.266,2.601) E55(-33.393,2.601) E57(-34.774,2.601) E63(-38.628,2.647) F1(0,3.436) F22(-12.717,3.058) F24(-14.023,3.126) F26(-15.277,3.126) F28(-16.531,3.126) F30(-17.785,3.126) F32(-19.038,3.126) F34(-20.292,3.126) F36(-21.546,3.126) F38(-22.8,3.126) F40(-24.053,3.126) F42(-25.307,3.126) F44(-26.561,3.126) F46(-27.815,3.126) F48(-29.068,3.126) F50(-30.322,3.126) F52(-31.576,3.126) F54(-32.83,3.126) F56(-34.083,3.126) F58(-35.377,3.126) G22(-12.607,3.768) G23(-13.333,3.451) G25(-14.714,3.451) G27(-15.84,3.451) G29(-17.221,3.451) G31(-18.348,3.451) G33(-19.729,3.451) G35(-20.855,3.451) G37(-22.236,3.451) G39(-23.363,3.451) G41(-24.744,3.451) G43(-25.87,3.451) G45(-27.251,3.451) G47(-28.378,3.451) G49(-29.759,3.451) G51(-30.885,3.451) G53(-32.266,3.451) G55(-33.393,3.451) G57(-34.774,3.451) H22(-12.607,4.581) H23(-13.115,4.174) H57(-35.057,4.101) J22(-12.607,5.393) J23(-13.115,4.987) J58(-35.377,4.827) K9(-5.032,5.861) K10(-5.935,5.7) K12(-6.888,5.7) K14(-7.84,5.7) K16(-8.793,5.7) K18(-9.745,5.7) K19(-10.698,5.7) K21(-11.65,5.7) K23(-13.115,5.8) K57(-35.057,5.478) L10(-5.476,6.338) L11(-6.412,6.144) L13(-7.364,6.144) L15(-8.317,6.144) L17(-9.269,6.144) L18(-10.222,6.144) L20(-11.18,6.206) L22(-12.607,6.206) L58(-35.377,6.128) M9(-5.032,6.814) M20(-11.18,7.019) M21(-11.688,6.613) M22(-12.607,7.019) M23(-13.115,6.613) M57(-35.057,6.778) N10(-5.476,7.29) N21(-11.688,7.425) N23(-13.115,7.425) N58(-35.377,7.428) P9(-5.032,7.766) P20(-11.18,7.832) P22(-12.607,7.832) P57(-35.057,8.078) R10(-5.476,8.243) R20(-11.18,8.645) R21(-11.688,8.238) R22(-12.607,8.645) R23(-13.115,8.238) T9(-5.032,8.719) T21(-11.688,9.051) T23(-13.115,9.051) T58(-35.377,8.729) U9(-5.032,9.671) U10(-5.476,9.195) U20(-11.18,9.457) U22(-12.607,9.457) U57(-35.057,9.379) V10(-5.476,10.148) V21(-11.688,9.864) V23(-13.115,9.864) V58(-35.377,10.029) W9(-5.032,10.624) W20(-11.18,10.27) W21(-11.688,10.677) W22(-12.607,10.27) W23(-13.115,10.677) W57(-35.057,10.679) Y10(-5.476,11.1) Y20(-11.18,11.083) Y22(-12.607,11.083)
  round 0.305 smd: A8(-4.538,0) A9(-5.452,0) A11(-6.367,0) A12(-7.116,0) A14(-8.03,0) A15(-8.945,0) A17(-9.694,0) A18(-10.608,0) A20(-11.523,0) A21(-12.272,0) A23(-13.186,0) A24(-14.023,0.325) A25(-14.714,0) A27(-15.84,0) A28(-16.531,0.325) A29(-17.221,0) A31(-18.348,0) A32(-19.038,0.325) A33(-19.729,0) A35(-20.855,0) A36(-21.546,0.325) A37(-22.236,0) A39(-23.363,0) A40(-24.053,0.325) A41(-24.744,0) A43(-25.87,0) A44(-26.561,0.325) A45(-27.251,0) A47(-28.378,0) A48(-29.068,0.325) A49(-29.759,0) A51(-30.885,0) A52(-31.576,0.325) A53(-32.266,0) A55(-33.393,0) A56(-34.083,0.325) A57(-34.774,0) AA1(0,11.717) AA2(-0.65,11.717) AA3(-1.3,11.678) AA4(-1.951,11.678) AA59(-36.027,11.638) AA60(-36.678,11.638) AA61(-37.328,11.638) AA62(-37.978,11.676) AA63(-38.628,11.676) AB5(-2.637,12.053) AB6(-3.287,12.053) AB7(-3.937,12.053) AB8(-4.587,12.053) AC1(0,12.466) AC2(-0.65,12.466) AC3(-1.3,12.504) AC4(-1.951,12.504) AC59(-36.027,12.464) AC60(-36.678,12.464) AC61(-37.328,12.464) AC62(-37.978,12.426) AC63(-38.628,12.426) AD1(0,13.215) AD2(-0.65,13.215) AD3(-1.3,13.177) AD4(-1.951,13.177) AD5(-2.637,13.005) AD6(-3.287,13.005) AD7(-3.937,13.005) AD8(-4.587,13.005) AD59(-36.027,13.137) AD60(-36.678,13.137) AD61(-37.328,13.137) AD62(-37.978,13.175) AD63(-38.628,13.175) AE5(-2.637,13.958) AE6(-3.287,13.958) AE7(-3.937,13.958) AE8(-4.587,13.958) AE59(-36.027,13.962) AE60(-36.678,13.962) AE61(-37.328,13.962) AE62(-37.978,13.924) AE63(-38.628,13.924) AF1(0,13.964) AF2(-0.65,13.964) AF3(-1.3,14.003) AF4(-1.951,14.003) AG1(0,14.714) AG2(-0.65,14.714) AG3(-1.3,14.676) AG4(-1.951,14.676) AG5(-2.637,14.91) AG6(-3.287,14.91) AG7(-3.937,14.91) AG8(-4.587,14.91) AG21(-11.955,15.122) AG60(-36.352,14.602) AG61(-37.003,14.602) AG62(-37.653,14.602) AG63(-38.303,14.602) AH1(0,15.463) AH2(-0.65,15.463) AH3(-1.3,15.501) AH4(-1.951,15.501) AH10(-5.653,15.476) AH11(-6.465,15.476) AH13(-7.278,15.476) AH14(-8.091,15.476) AH16(-8.904,15.476) AH17(-9.717,15.476) AH19(-10.529,15.476) AH20(-11.342,15.476) AH60(-36.678,15.278) AH61(-37.328,15.278) AH62(-37.978,15.278) AH63(-38.628,15.278) AJ5(-2.637,15.863) AJ6(-3.287,15.863) AJ7(-3.937,15.863) AJ8(-4.587,15.863) AJ10(-5.653,16.126) AJ11(-6.465,16.126) AJ13(-7.278,16.126) AJ14(-8.091,16.126) AJ60(-36.352,15.954) AJ61(-37.003,15.954) AJ62(-37.653,15.954) AJ63(-38.303,15.954) AK1(0,16.212) AK2(-0.65,16.212) AK3(-1.3,16.174) AK4(-1.951,16.174) AK8(-4.303,16.451) AK18(-9.848,16.266) AK20(-10.801,16.266) AK21(-11.753,16.266) AK60(-36.678,16.523) AK61(-37.328,16.523) AK62(-37.978,16.629) AK63(-38.628,16.629) AL1(0,16.962) AL2(-0.65,16.962) AL3(-1.3,17) AL4(-1.951,17) AL5(-2.901,16.776) AL7(-3.739,16.776) AL8(-4.303,17.101) AL10(-5.658,16.776) AL11(-6.221,17.101) AL13(-7.576,16.776) AL15(-8.14,17.101) AL17(-9.222,16.583) AL18(-9.848,16.916) AL20(-10.801,16.916) AL21(-11.753,16.916) AL22(-12.706,16.916) AL23(-13.529,16.916) AL25(-14.504,16.916) AL26(-15.456,16.916) AL28(-16.409,16.916) AL29(-17.361,16.916) AL31(-18.26,16.591) AL32(-18.824,16.916) AL33(-19.726,16.916) AL35(-20.729,16.916) AL36(-21.58,16.916) AL38(-22.634,16.916) AL39(-23.542,16.591) AL40(-24.131,16.916) AL42(-24.944,16.916) AL43(-25.897,16.916) AL45(-26.874,16.916) AL46(-27.802,16.916) AL48(-28.856,16.916) AL49(-29.757,16.916) AL51(-30.761,16.916) AL52(-31.583,16.916) AL54(-32.61,16.916) AL55(-33.562,16.916) AL57(-34.509,16.916) AL58(-35.408,16.916) AL60(-36.352,17.169) AL61(-37.003,17.169) AM1(0,17.711) AM2(-0.65,17.711) AM3(-1.3,17.673) AM4(-1.951,17.673) AM5(-2.901,17.426) AM7(-3.739,17.426) AM8(-4.303,17.752) AM10(-5.658,17.426) AM11(-6.221,17.752) AM13(-7.576,17.426) AM15(-8.14,17.752) AM17(-9.222,17.233) AM18(-9.848,17.567) AM20(-10.801,17.567) AM21(-11.753,17.567) AM22(-12.706,17.567) AM23(-13.529,17.567) AM25(-14.504,17.567) AM26(-15.456,17.567) AM28(-16.409,17.567) AM29(-17.361,17.567) AM31(-18.26,17.242) AM32(-18.824,17.567) AM33(-19.726,17.567) AM35(-20.729,17.567) AM36(-21.58,17.567) AM38(-22.634,17.567) AM40(-24.131,17.567) AM42(-24.944,17.567) AM43(-25.897,17.567) AM45(-26.874,17.567) AM46(-27.802,17.567) AM48(-28.856,17.567) AM49(-29.757,17.567) AM51(-30.761,17.567) AM52(-31.583,17.567) AM54(-32.61,17.567) AM55(-33.562,17.567) AM57(-34.509,17.567) AM58(-35.408,17.567) AM60(-36.678,17.816) AM61(-37.328,17.816) AM62(-37.978,17.709) AM63(-38.628,17.709) AN1(0,18.46) AN2(-0.65,18.46) AN3(-1.3,18.498) AN4(-1.951,18.498) AN5(-2.901,18.077) AN7(-3.739,18.077) AN8(-4.303,18.402) AN10(-5.658,18.077) AN11(-6.221,18.402) AN13(-7.576,18.077) AN15(-8.14,18.402) AN17(-9.222,17.883) AN18(-9.848,18.217) AN20(-10.801,18.217) AN21(-11.753,18.217) AN22(-12.706,18.217) AN23(-13.529,18.217) AN25(-14.504,18.217) AN26(-15.456,18.217) AN28(-16.409,18.217) AN29(-17.361,18.217) AN31(-18.26,17.892) AN32(-18.824,18.217) AN33(-19.726,18.217) AN35(-20.729,18.217) AN36(-21.58,18.217) AN38(-22.634,18.217) AN39(-23.542,17.892) AN40(-24.131,18.217) AN42(-24.944,18.217) AN43(-25.897,18.217) AN45(-26.874,18.217) AN46(-27.802,18.217) AN48(-28.856,18.217) AN49(-29.757,18.217) AN51(-30.761,18.217) AN52(-31.583,18.217) AN54(-32.61,18.217) AN55(-33.562,18.217) AN57(-34.509,18.217) AN58(-35.408,18.217) AN60(-36.352,18.385) AN61(-37.003,18.385) AN62(-37.653,18.385) AN63(-38.303,18.385) AP1(0,19.21) AP2(-0.65,19.21) AP3(-1.3,19.171) AP4(-1.951,19.171) AP5(-2.901,18.727) AP7(-3.739,18.727) AP8(-4.303,19.052) AP10(-5.658,18.727) AP11(-6.221,19.052) AP13(-7.576,18.727) AP15(-8.14,19.052) AP17(-9.222,18.533) AP18(-9.848,18.867) AP20(-10.801,18.867) AP21(-11.753,18.867) AP22(-12.706,18.867) AP23(-13.529,18.867) AP25(-14.504,18.867) AP26(-15.456,18.867) AP28(-16.409,18.867) AP29(-17.361,18.867) AP31(-18.26,18.542) AP32(-18.824,18.867) AP33(-19.726,18.867) AP35(-20.729,18.867) AP36(-21.58,18.867) AP38(-22.634,18.867) AP39(-23.542,18.542) AP40(-24.131,18.867) AP42(-24.944,18.867) AP43(-25.897,18.867) AP45(-26.874,18.867) AP46(-27.802,18.867) AP48(-28.856,18.867) AP49(-29.757,18.867) AP51(-30.761,18.867) AP52(-31.583,18.867) AP54(-32.61,18.867) AP55(-33.562,18.867) AP57(-34.509,18.867) AP58(-35.408,18.867) AP60(-36.678,19.06) AP61(-37.328,19.06) AP62(-37.978,19.06) AP63(-38.628,19.06) AR5(-2.901,19.377) AR7(-3.739,19.377) AR8(-4.303,19.702) AR10(-5.658,19.377) AR11(-6.221,19.702) AR13(-7.576,19.377) AR15(-8.14,19.702) AR17(-9.222,19.184) AR18(-9.848,19.517) AR20(-10.801,19.517) AR21(-11.753,19.517) AR22(-12.706,19.517) AR23(-13.529,19.517) AR25(-14.504,19.517) AR26(-15.456,19.517) AR28(-16.409,19.517) AR29(-17.361,19.517) AR31(-18.26,19.192) AR32(-18.824,19.517) AR33(-19.726,19.517) AR35(-20.729,19.517) AR36(-21.58,19.517) AR38(-22.634,19.517) AR39(-23.542,19.192) AR40(-24.131,19.517) AR42(-24.944,19.517) AR43(-25.897,19.517) AR45(-26.874,19.517) AR46(-27.802,19.517) AR48(-28.856,19.517) AR49(-29.757,19.517) AR51(-30.761,19.517) AR52(-31.583,19.517) AR54(-32.61,19.517) AR55(-33.562,19.517) AR57(-34.509,19.517) AR58(-35.408,19.517) AT2(-0.65,19.959) AT3(-1.3,19.997) AT4(-1.951,19.997) AT5(-2.901,20.027) AT7(-3.739,20.027) AT10(-5.658,20.027) AT13(-7.576,20.027) AT35(-20.437,20.22) AT37(-22.011,20.22) AT40(-23.586,20.22) AT42(-25.161,20.22) AT43(-26.736,20.22) AT46(-28.311,20.22) AT49(-29.912,20.248) AT61(-37.003,19.634) AT62(-37.812,19.69) AU2(-0.655,20.647) AU3(-1.315,20.647) AU4(-1.976,20.647) AU6(-3.337,20.678) AU7(-4.163,20.678) AU8(-4.836,20.678) AU10(-5.661,20.678) AU11(-6.335,20.678) AU12(-7.16,20.678) AU14(-7.833,20.678) AU15(-8.659,20.678) AU16(-9.222,20.353) AU17(-9.86,20.678) AU18(-10.536,20.353) AU19(-11.105,20.678) AU20(-11.751,20.353) AU21(-12.397,20.678) AU22(-12.966,20.353) AU23(-13.642,20.678) AU24(-14.318,20.353) AU25(-14.993,20.678) AU26(-15.669,20.353) AU27(-16.238,20.678) AU28(-16.884,20.353) AU29(-17.531,20.678) AU30(-18.1,20.353) AU31(-18.775,20.678) AU33(-19.372,20.33) AU34(-19.974,20.678) AU35(-20.899,20.678) AU36(-21.549,20.678) AU37(-22.474,20.678) AU39(-23.124,20.678) AU40(-24.048,20.678) AU41(-24.699,20.678) AU42(-25.623,20.678) AU43(-26.274,20.678) AU44(-27.198,20.678) AU46(-27.848,20.678) AU47(-28.773,20.678) AU49(-29.423,20.678) AU50(-30.4,20.678) AU51(-30.98,20.353) AU52(-31.656,20.678) AU53(-32.331,20.353) AU54(-32.9,20.678) AU55(-33.547,20.353) AU56(-34.193,20.678) AU57(-34.762,20.353) AU58(-35.438,20.678) AU59(-36.002,20.353) AU60(-36.566,20.678) AU61(-37.277,20.401) AU62(-37.978,20.663) AV3(-1.321,21.308) AV4(-1.976,21.308) AV5(-2.664,21.328) AV6(-3.337,21.328) AV7(-4.163,21.328) AV8(-4.836,21.328) AV10(-5.661,21.328) AV11(-6.335,21.328) AV12(-7.16,21.328) AV14(-7.833,21.328) AV15(-8.659,21.328) AV16(-9.222,21.003) AV17(-9.86,21.328) AV18(-10.536,21.003) AV19(-11.105,21.328) AV20(-11.751,21.003) AV21(-12.397,21.328) AV22(-12.966,21.003) AV23(-13.642,21.328) AV24(-14.318,21.003) AV25(-14.993,21.328) AV26(-15.669,21.003) AV27(-16.238,21.328) AV28(-16.884,21.003) AV29(-17.531,21.328) AV30(-18.1,21.003) AV31(-18.775,21.328) AV33(-19.4,21.003) AV34(-20.024,21.328) AV35(-20.849,21.328) AV36(-21.599,21.328) AV37(-22.424,21.328) AV39(-23.173,21.328) AV40(-23.999,21.328) AV41(-24.748,21.328) AV42(-25.574,21.328) AV43(-26.323,21.328) AV44(-27.149,21.328) AV46(-27.898,21.328) AV47(-28.723,21.328) AV49(-29.473,21.328) AV50(-30.298,21.328) AV51(-30.98,21.003) AV52(-31.656,21.328) AV53(-32.331,21.003) AV54(-32.9,21.328) AV55(-33.547,21.003) AV56(-34.193,21.328) AV57(-34.762,21.003) AV58(-35.438,21.328) AV59(-36.002,21.003) AV60(-36.566,21.328) AV61(-37.302,21.051) AW4(-1.976,21.968) AW5(-2.626,21.978) AW6(-3.375,21.978) AW7(-4.125,21.978) AW8(-4.874,21.978) AW10(-5.623,21.978) AW11(-6.373,21.978) AW12(-7.122,21.978) AW14(-7.871,21.978) AW15(-8.621,21.978) AW16(-9.222,21.653) AW17(-9.86,21.978) AW18(-10.536,21.653) AW19(-11.211,21.978) AW21(-12.291,21.978) AW22(-12.966,21.653) AW23(-13.642,21.978) AW24(-14.318,21.653) AW25(-14.993,21.978) AW26(-15.669,21.653) AW27(-16.345,21.978) AW29(-17.424,21.978) AW30(-18.1,21.653) AW31(-18.775,21.978) AW33(-19.451,21.653) AW34(-20.024,21.978) AW35(-20.849,21.978) AW36(-21.599,21.978) AW37(-22.424,21.978) AW39(-23.173,21.978) AW40(-23.999,21.978) AW41(-24.748,21.978) AW42(-25.574,21.978) AW43(-26.323,21.978) AW44(-27.149,21.978) AW46(-27.898,21.978) AW47(-28.723,21.978) AW49(-29.473,21.978) AW50(-30.298,21.978) AW51(-30.98,21.653) AW52(-31.656,21.978) AW53(-32.331,21.653) AW54(-33.007,21.978) AW56(-34.087,21.978) AW57(-34.762,21.653) AW58(-35.438,21.978) AW59(-36.002,21.653) AW60(-36.566,21.978) AY6(-3.375,22.628) AY7(-4.125,22.628) AY8(-4.874,22.628) AY10(-5.623,22.628) AY11(-6.373,22.628) AY12(-7.122,22.628) AY14(-7.871,22.628) AY15(-8.621,22.628) AY16(-9.184,22.303) AY17(-9.86,22.628) AY18(-10.536,22.303) AY19(-11.211,22.628) AY21(-12.291,22.628) AY22(-12.966,22.303) AY23(-13.642,22.628) AY24(-14.318,22.303) AY25(-14.993,22.628) AY26(-15.669,22.303) AY27(-16.345,22.628) AY29(-17.424,22.628) AY30(-18.1,22.303) AY31(-18.775,22.628) AY33(-19.451,22.303) AY34(-20.024,22.628) AY35(-20.849,22.628) AY36(-21.599,22.628) AY37(-22.424,22.628) AY39(-23.173,22.628) AY40(-23.999,22.628) AY41(-24.748,22.628) AY42(-25.574,22.628) AY43(-26.323,22.628) AY44(-27.149,22.628) AY46(-27.898,22.628) AY47(-28.723,22.628) AY49(-29.473,22.628) AY50(-30.298,22.628) AY51(-30.98,22.303) AY52(-31.656,22.628) AY53(-32.331,22.303) AY54(-33.007,22.628) AY56(-34.087,22.628) AY57(-34.762,22.303) AY58(-35.438,22.628) B4(-1.922,0.65) B5(-3.138,0.643) B6(-4.119,0.643) B8(-4.891,0.643) B9(-5.716,0.643) B11(-6.697,0.643) B12(-7.469,0.643) B14(-8.294,0.643) B15(-9.275,0.643) B17(-10.047,0.643) B18(-10.872,0.643) B20(-11.853,0.643) B21(-12.272,1.196) B22(-12.625,0.643) B23(-13.451,0.643) B24(-14.023,0.975) B25(-14.714,0.65) B26(-15.277,0.975) B27(-15.84,0.65) B28(-16.531,0.975) B29(-17.221,0.65) B30(-17.785,0.975) B31(-18.348,0.65) B32(-19.038,0.975) B33(-19.729,0.65) B34(-20.292,0.975) B35(-20.855,0.65) B36(-21.546,0.975) B37(-22.236,0.65) B38(-22.8,0.975) B39(-23.363,0.65) B40(-24.053,0.975) B41(-24.744,0.65) B42(-25.307,0.975) B43(-25.87,0.65) B44(-26.561,0.975) B45(-27.251,0.65) B46(-27.815,0.975) B47(-28.378,0.65) B48(-29.068,0.975) B49(-29.759,0.65) B50(-30.322,0.975) B51(-30.885,0.65) B52(-31.576,0.975) B53(-32.266,0.65) B54(-32.83,0.975) B55(-33.393,0.65) B56(-34.083,0.975) B57(-34.774,0.65) B58(-35.337,0.975) B59(-35.9,0.65) B60(-36.665,0.66) C3(-1.302,1.302) C4(-2.118,1.272) C5(-2.772,1.196) C6(-3.776,1.196) C8(-4.538,1.196) C9(-5.351,1.196) C11(-6.354,1.196) C12(-7.116,1.196) C14(-7.929,1.196) C15(-8.932,1.196) C17(-9.694,1.196) C18(-10.507,1.196) C20(-11.51,1.196) C21(-11.891,1.786) C22(-12.678,1.786) C23(-13.085,1.196) C24(-14.051,2.032) C25(-14.714,1.3) C26(-15.277,1.626) C27(-15.84,1.3) C28(-16.558,2.032) C29(-17.221,1.3) C30(-17.785,1.626) C31(-18.348,1.3) C32(-19.066,2.032) C33(-19.729,1.3) C34(-20.292,1.626) C35(-20.855,1.3) C36(-21.573,2.032) C37(-22.236,1.3) C38(-22.8,1.626) C39(-23.363,1.3) C40(-24.081,2.032) C41(-24.744,1.3) C42(-25.307,1.626) C43(-25.87,1.3) C44(-26.588,2.032) C45(-27.251,1.3) C46(-27.815,1.626) C47(-28.378,1.3) C48(-29.07,2.032) C49(-29.759,1.3) C50(-30.322,1.626) C51(-30.885,1.3) C52(-31.578,1.991) C53(-32.266,1.3) C54(-32.83,1.626) C55(-33.393,1.3) C56(-34.085,1.991) C57(-34.774,1.3) C58(-35.337,1.626) C59(-35.9,1.3) C61(-37.003,1.237) D2(-0.65,2.075) D3(-1.3,2.037) D5(-2.678,1.842) D6(-3.369,1.786) D8(-4.157,1.786) D9(-4.944,1.786) D11(-5.852,1.786) D12(-6.735,1.786) D14(-7.522,1.786) D15(-8.43,1.786) D17(-9.313,1.786) D18(-10.1,1.786) D20(-11.008,1.786) D21(-12.235,2.423) D23(-13.377,1.786) D25(-14.714,1.951) D26(-15.277,2.276) D27(-15.84,1.951) D29(-17.221,1.951) D30(-17.785,2.276) D31(-18.348,1.951) D33(-19.729,1.951) D34(-20.292,2.276) D35(-20.855,1.951) D37(-22.236,1.951) D38(-22.8,2.276) D39(-23.363,1.951) D41(-24.744,1.951) D42(-25.307,2.276) D43(-25.87,1.951) D45(-27.251,1.951) D46(-27.815,2.276) D47(-28.378,1.951) D49(-29.759,1.951) D50(-30.322,2.276) D51(-30.885,1.951) D53(-32.266,1.951) D54(-32.83,2.276) D55(-33.393,1.951) D57(-34.774,1.951) D58(-35.337,2.276) D59(-35.9,1.951) D60(-36.678,1.801) D61(-37.328,1.801) D62(-37.978,2.035) E2(-0.65,2.725) E3(-1.3,2.687) E4(-1.951,2.687) E5(-2.602,2.619) E6(-3.554,2.619) E8(-4.507,2.619) E10(-5.459,2.619) E11(-6.412,2.619) E13(-7.364,2.619) E15(-8.317,2.619) E17(-9.269,2.619) E18(-10.222,2.619) E20(-11.174,2.619) E59(-36.027,2.647) E60(-36.678,2.647) E61(-37.328,2.647) E62(-37.978,2.685) F2(-0.65,3.474) F3(-1.3,3.512) F4(-1.951,3.512) F5(-2.602,3.269) F6(-3.554,3.269) F8(-4.507,3.269) F10(-5.459,3.269) F11(-6.412,3.269) F13(-7.364,3.269) F15(-8.317,3.269) F17(-9.269,3.269) F18(-10.222,3.269) F20(-11.174,3.269) F59(-36.027,3.472) F60(-36.678,3.472) F61(-37.328,3.472) F62(-37.978,3.434) F63(-38.628,3.434) G1(0,4.224) G2(-0.65,4.224) G3(-1.3,4.185) G4(-1.951,4.185) G5(-2.602,3.919) G6(-3.554,3.919) G8(-4.507,3.919) G10(-5.459,3.919) G11(-6.412,3.919) G13(-7.364,3.919) G15(-8.317,3.919) G17(-9.269,3.919) G18(-10.222,3.919) G20(-11.174,3.919) H5(-2.602,4.569) H6(-3.554,4.569) H8(-4.507,4.569) H10(-5.459,4.569) H11(-6.412,4.569) H13(-7.364,4.569) H15(-8.317,4.569) H17(-9.269,4.569) H18(-10.222,4.569) H20(-11.174,4.569) H59(-36.027,4.145) H60(-36.678,4.145) H61(-37.328,4.145) H62(-37.978,4.183) H63(-38.628,4.183) J1(0,4.973) J2(-0.65,4.973) J3(-1.3,5.011) J4(-1.951,5.011) J5(-2.627,5.22) J6(-3.567,5.22) J8(-4.507,5.22) J10(-5.459,5.22) J11(-6.412,5.22) J13(-7.364,5.22) J15(-8.317,5.22) J17(-9.269,5.22) J18(-10.222,5.22) J20(-11.174,5.22) J21(-12.095,4.986) J59(-36.027,4.971) J60(-36.678,4.971) J61(-37.328,4.971) J62(-37.978,4.933) J63(-38.628,4.933) K1(0,5.722) K2(-0.65,5.722) K3(-1.3,5.684) K4(-1.951,5.684) K59(-36.027,5.644) K60(-36.678,5.644) K61(-37.328,5.644) K62(-37.978,5.682) K63(-38.628,5.682) L1(0,6.471) L2(-0.65,6.471) L3(-1.3,6.51) L4(-1.951,6.51) L5(-2.637,6.338) L6(-3.287,6.338) L7(-3.937,6.338) L8(-4.587,6.338) L59(-36.027,6.469) L60(-36.678,6.469) L61(-37.328,6.469) L62(-37.978,6.431) L63(-38.628,6.431) N1(0,7.221) N2(-0.65,7.221) N3(-1.3,7.183) N4(-1.951,7.183) N5(-2.637,7.29) N6(-3.287,7.29) N7(-3.937,7.29) N8(-4.587,7.29) N59(-36.027,7.142) N60(-36.678,7.142) N61(-37.328,7.142) N62(-37.978,7.181) N63(-38.628,7.181) P1(0,7.97) P2(-0.65,7.97) P3(-1.3,8.008) P4(-1.951,8.008) P59(-36.027,7.968) P60(-36.678,7.968) P61(-37.328,7.968) P62(-37.978,7.93) P63(-38.628,7.93) R5(-2.637,8.243) R6(-3.287,8.243) R7(-3.937,8.243) R8(-4.587,8.243) T1(0,8.719) T2(-0.65,8.719) T3(-1.3,8.681) T4(-1.951,8.681) T59(-36.027,8.641) T60(-36.678,8.641) T61(-37.328,8.641) T62(-37.978,8.679) T63(-38.628,8.679) U1(0,9.469) U2(-0.65,9.469) U3(-1.3,9.507) U4(-1.951,9.507) U5(-2.637,9.195) U6(-3.287,9.195) U7(-3.937,9.195) U8(-4.587,9.195) U59(-36.027,9.467) U60(-36.678,9.467) U61(-37.328,9.467) U62(-37.978,9.428) U63(-38.628,9.428) V1(0,10.218) V2(-0.65,10.218) V3(-1.3,10.18) V4(-1.951,10.18) V5(-2.637,10.148) V6(-3.287,10.148) V7(-3.937,10.148) V8(-4.587,10.148) V59(-36.027,10.14) V60(-36.678,10.14) V61(-37.328,10.14) V62(-37.978,10.178) V63(-38.628,10.178) Y1(0,10.967) Y2(-0.65,10.967) Y3(-1.3,11.005) Y4(-1.951,11.005) Y5(-2.637,11.1) Y6(-3.287,11.1) Y7(-3.937,11.1) Y8(-4.587,11.1) Y59(-36.027,10.965) Y60(-36.678,10.965) Y61(-37.328,10.965) Y62(-37.978,10.927) Y63(-38.628,10.927)
  round 0.33 smd: AK22(-12.655,16.266) AK23(-13.529,16.266) AK25(-14.504,16.266) AK26(-15.456,16.266) AK28(-16.409,16.266) AK29(-17.311,16.266) AK32(-18.824,16.266) AK33(-19.726,16.266) AK35(-20.729,16.266) AK36(-21.58,16.266) AK38(-22.609,16.266) AK40(-24.106,16.266) AK42(-24.944,16.266) AK43(-25.897,16.266) AK45(-26.874,16.266) AK46(-27.776,16.266) AK48(-28.83,16.266) AK49(-29.732,16.266) AK51(-30.735,16.266) AK52(-31.583,16.266) AK54(-32.61,16.266) AK55(-33.562,16.266) AK57(-34.509,16.266) AK58(-35.408,16.266)
